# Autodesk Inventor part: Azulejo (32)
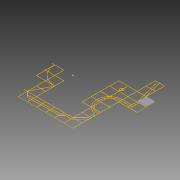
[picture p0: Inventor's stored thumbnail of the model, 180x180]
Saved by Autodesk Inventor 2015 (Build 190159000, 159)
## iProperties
Created: 2015-04
Part Number: Azulejo (32)
Material: Genérico
Document SubType Name: Modeling
Designer: Felipe
Density: 1 g/cm^3
Appearance: Padrão
Author: Felipe
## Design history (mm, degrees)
sketch "Sketch1"
  geometry: L1 (-1510, -7490)-(-1510, -6010); L2 (-3010, -1490)-(-3010, -10); L3 (-2990, 10)-(-1510, 10); L4 (-1510, -10)-(-2990, -10); L5 (-1510, -1490)-(-1510, -10); L6 (-1490, -10)-(-1490, -1490); L7 (-1490, -1490)-(-10, -1490); L8 (-10, -1510)-(-1490, -1510); L9 (-10, -2990)-(-10, -1510); L10 (-10, -5990)-(-10, -4510); L11 (-1490, -7490)-(-10, -7490); L12 (4490, -6010)-(3010, -6010); L13 (10, -1510)-(10, -2990); L14 (10, -3010)-(10, -4490); L15 (10, -4510)-(10, -5990); L16 (10, -5990)-(1490, -5990); L17 (1490, -6010)-(10, -6010); L18 (10, -7490)-(1490, -7490); L19 (1510, -5990)-(2990, -5990); L20 (2990, -6010)-(1510, -6010); L21 (1510, -7490)-(2990, -7490); L22 (4490, 1510)-(4490, 2990); L23 (4490, 10)-(4490, 1490); L24 (4490, -1490)-(4490, -10); L25 (4490, -2990)-(4490, -1510); L26 (3010, -5990)-(4490, -5990); L27 (3010, -7490)-(4490, -7490); L28 (4510, 3010)-(5990, 3010); L29 (5990, 2990)-(4510, 2990); L30 (4510, 2990)-(4510, 1510); L31 (4510, 1510)-(5990, 1510); L32 (5990, 1510)-(5990, 1740.185); L33 (5990, 1760.2)-(5990, 2259.8); L34 (5990, 2279.815)-(5990, 2990); L35 (5990, 1490)-(4510, 1490); L36 (4510, 1490)-(4510, 10); L37 (4510, 10)-(5990, 10); L38 (5990, 10)-(5990, 1490); L39 (5975.983, -10)-(4510, -10); L40 (4510, -10)-(4510, -1490); L41 (5990, -1510)-(5782.897, -1510); L42 (5782.897, -1510)-(5688.66, -1510); L43 (5668.66, -1510)-(5482.895, -1510); L44 (5482.895, -1510)-(5388.656, -1510); L45 (5368.656, -1510)-(4510, -1510); L46 (4510, -1510)-(4510, -2990); L47 (4510, -2990)-(5975.983, -2990); L48 (5990, -2975.728)-(5990, -2837.377); L49 (5990, -2837.377)-(5990, -2536.247); L50 (5990, -2500.476)-(5990, -2317.632); L51 (5990, -2317.632)-(5990, -1510); L52 (5990, -3010)-(4510, -3010); L53 (5990, -4490)-(5990, -3010); L54 (4510, -5990)-(5990, -5990); L55 (5990, -5990)-(5990, -4510); L56 (4510, -7490)-(5990, -7490); L57 (5990, -7490)-(5990, -6310); L58 (5990, -6290)-(5990, -6010); L59 (7490, 4510)-(7490, 5990); L60 (6010, 3010)-(7490, 3010); L61 (7490, 3010)-(7490, 4490); L62 (7490, 2990)-(6010, 2990); L63 (6010, 2990)-(6010, 2279.815); L64 (6010, 2259.8)-(6010, 1760.2)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; A1 r 250 centre (6000, 2010) between (5990, 2259.8) and (5990, 1760.2); A2 r 250 centre (6000, 2010) between (6010, 1760.2) and (6010, 2259.8); A3 r 270 centre (6000, 2010) between (5990, 2279.815) and (5990, 1740.185); A4 r 270 centre (6000, 2010) between (6010, 1740.185) and (6010, 2279.815); A5 r 3010.017 centre (0, 0) between (-1490, -2615.358) and (-346.554, -2990); A6 r 2990.017 centre (0, 0) between (-1490, -2592.316) and (-10, -2990); A7 r 3010.017 centre (0, 0) between (-2603.863, -1510) and (-1510, -2603.863); A8 r 2990.017 centre (0, 0) between (-2580.717, -1510) and (-1510, -2580.717); A9 r 3010.017 centre (0, 0) between (-2990, -346.554) and (-2615.358, -1490); A10 r 2990.017 centre (0, 0) between (-2990, -10) and (-2592.316, -1490); A11 r 2131.367 centre (7500, -1500) between (7490, 631.344) and (6010, 24.017); A12 r 2131.367 centre (7500, -1500) between (5975.983, -10) and (5368.656, -1490); A13 r 2131.367 centre (7500, -1500) between (5368.656, -1510) and (5975.983, -2990); A14 r 2131.367 centre (7500, -1500) between (6010, -3024.017) and (7190, -3608.703); A15 r 1831.367 centre (7500, -1500) between (7490.321, 331.342) and (6463.753, 10); A16 r 1831.367 centre (7500, -1500) between (6435.196, -10) and (6010, -435.196); A17 r 1831.367 centre (7500, -1500) between (5990, -463.753) and (5668.66, -1490); A18 r 1831.367 centre (7500, -1500) between (5668.66, -1510) and (5990, -2536.247); A19 r 1831.367 centre (7500, -1500) between (6010, -2564.804) and (6435.196, -2990); A20 r 1831.367 centre (7500, -1500) between (6463.753, -3010) and (7490, -3331.34); A21 r 2111.367 centre (7500, -1500) between (7490.047, 611.344) and (6024.272, 10); A22 r 2111.367 centre (7500, -1500) between (5990, -24.272) and (5388.656, -1490); A23 r 2111.367 centre (7500, -1500) between (5388.656, -1510) and (5990, -2975.728); A24 r 2111.367 centre (7500, -1500) between (6024.272, -3010) and (7210, -3591.357); A25 r 1811.367 centre (7500, -1500) between (7490.374, 311.342) and (6499.524, 10); A26 r 1811.367 centre (7500, -1500) between (6469.975, -10) and (6010, -469.975); A27 r 1811.367 centre (7500, -1500) between (5990, -499.524) and (5688.66, -1490); A28 r 1811.367 centre (7500, -1500) between (5688.66, -1510) and (5990, -2500.476); A29 r 1811.367 centre (7500, -1500) between (6010, -2530.025) and (6469.975, -2990); A30 r 1811.367 centre (7500, -1500) between (6499.524, -3010) and (7490, -3311.34); A31 r 449.871 centre (7499.449, -4060.672) between (7510, -4510.419) and (7521.546, -4510); 9 further points
  constraints: 698 end point, 64 point on circle, 31 centre point, 11 point on line, 1 other
extrude "Extrusion1" new body sketch "Sketch1" distance "d0" = 60; taper "d1" = 0 deg
extrude "Extrusion2" new body sketch "Sketch1" distance "d2" = 60; taper "d3" = 0 deg
body "Solid1"
body "Solid2"
